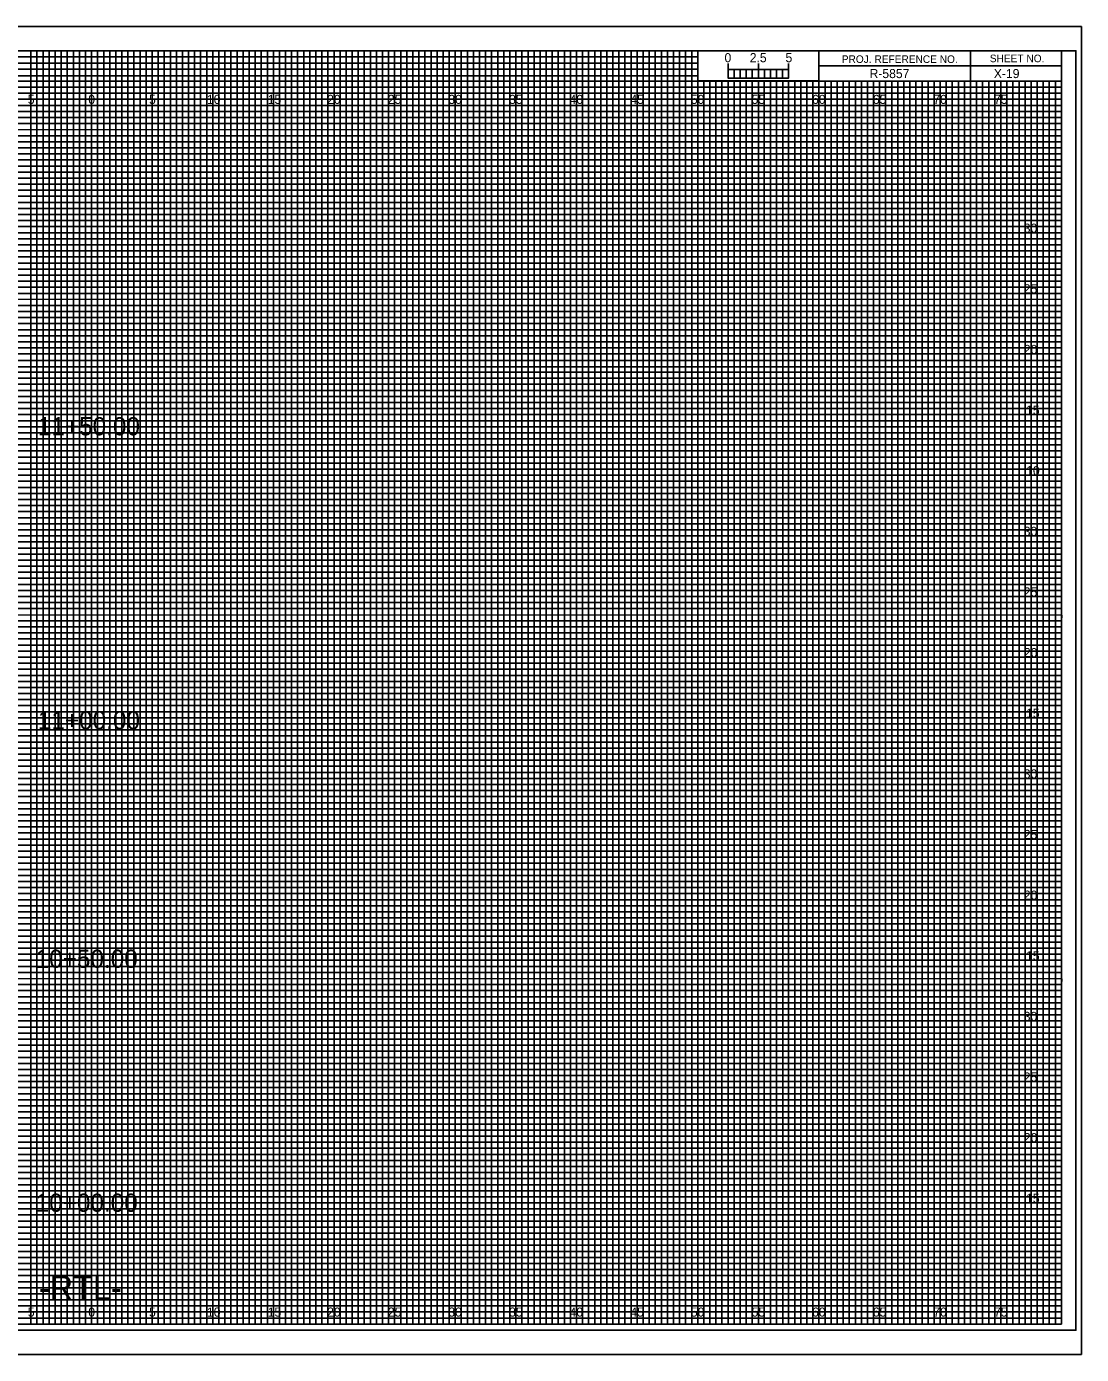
# Model space of a CAD drawing. Extents: x -7 to 162, y -3 to 107.
# Drawn here: x 74.6 to 161.7, y -2.5 to 107 of the extents above; entities that cross this region are included whole.
import ezdxf

# ---------------------------------------------------------------- set-up
doc = ezdxf.new("R2010")
doc.units = 0
for name, color, linetype in [('Exist Cross Section Cell', 7, 'Continuous'), ('Exist XS Center Line Elevation Label', 7, 'Continuous'), ('Exist XS Ground Line', 7, 'Continuous'), ('Prop CMT Pvmt Course 1', 7, 'Continuous'), ('Prop CMT Pvmt Course 1 Wedge', 7, 'Continuous'), ('Prop CMT Pvmt Course 2', 7, 'Continuous'), ('Prop CMT Pvmt Course 2 Wedge', 7, 'Continuous'), ('Prop CMT Pvmt Course 3', 7, 'Continuous'), ('Prop CMT Pvmt Course 3 Wedge', 7, 'Continuous'), ('Prop CMT Pvmt Surface', 7, 'Continuous'), ('Prop CMT Pvmt Surface Shoulder', 7, 'Continuous'), ('Prop CMT Shld Paved Course 1', 7, 'Continuous'), ('Prop CMT Shld Paved Course 2', 7, 'Continuous'), ('Prop CMT Shld Paved Course 3', 7, 'Continuous'), ('Prop CMT Slope Grass', 7, 'Continuous'), ('Prop CMT Subgrade Earthwork', 7, 'Continuous'), ('Scratch_Level_0', 7, 'Continuous')]:
    doc.layers.add(name, color=color, linetype=linetype)

msp = doc.modelspace()

# ---------------------------------------------------------------- linework, layer by layer
at = {"layer": 'Exist XS Center Line Elevation Label'}
for points in [[(72.5, 0), (77.5, 0), (77.5, 105), (82.5, 105), (82.5, 0), (87.5, 0), (87.5, 105), (92.5, 105), (92.5, 0), (97.5, 0), (97.5, 105), (102.5, 105), (102.5, 0), (107.5, 0), (107.5, 105), (112.5, 105), (112.5, 0), (117.5, 0), (117.5, 105), (122.5, 105), (122.5, 0), (127.5, 0), (127.5, 105), (129.97, 105), (130, 105), (130, 102.5), (132.5, 102.5), (132.5, 0), (137.5, 0), (137.5, 102.5), (142.5, 102.5), (142.5, 0), (147.5, 0), (147.5, 102.5), (152.5, 102.5), (152.5, 0), (157.5, 0), (157.5, 102.5)], [(0, 102.5), (137.5, 102.5)], [(0, 92.5), (160, 92.5), (160, 97.5), (0, 97.5)], [(0, 82.5), (160, 82.5), (160, 87.5), (0, 87.5)], [(0, 72.5), (160, 72.5), (160, 77.5), (0, 77.5)], [(0, 62.5), (160, 62.5), (160, 67.5), (0, 67.5)], [(0, 52.5), (160, 52.5), (160, 57.5), (0, 57.5)], [(0, 42.5), (160, 42.5), (160, 47.5), (0, 47.5)], [(0, 32.5), (160, 32.5), (160, 37.5), (0, 37.5)], [(0, 22.5), (160, 22.5), (160, 27.5), (0, 27.5)], [(0, 12.5), (160, 12.5), (160, 17.5), (0, 17.5)], [(0, 2.5), (160, 2.5), (160, 7.5), (0, 7.5)]]:
    msp.add_lwpolyline(points, dxfattribs=at)
at = {"layer": 'Exist XS Ground Line'}
for p, q in [((75, 105), (70, 105)), ((75, 0), (75, 105)), ((85, 105), (80, 105)), ((80, 105), (80, 0)), ((85, 0), (85, 105)), ((95, 105), (90, 105)), ((90, 105), (90, 0)), ((95, 0), (95, 105)), ((105, 105), (100, 105)), ((100, 105), (100, 0)), ((105, 0), (105, 105)), ((115, 105), (110, 105)), ((110, 105), (110, 0)), ((115, 0), (115, 105)), ((125, 105), (120, 105)), ((120, 105), (120, 0)), ((125, 0), (125, 105)), ((130, 105), (130, 0)), ((135, 0), (135, 102.5)), ((145, 102.5), (140, 102.5)), ((140, 102.5), (140, 0)), ((145, 0), (145, 102.5)), ((155, 102.5), (150, 102.5)), ((150, 102.5), (150, 0)), ((155, 0), (155, 102.5)), ((80, 0), (75, 0)), ((90, 0), (85, 0)), ((100, 0), (95, 0)), ((110, 0), (105, 0)), ((120, 0), (115, 0)), ((130, 0), (125, 0)), ((140, 0), (135, 0)), ((150, 0), (145, 0)), ((160, 0), (155, 0)), ((160, 0), (160, 0))]:
    msp.add_line(p, q, dxfattribs=at)
for points in [[(0, 100), (160, 100), (160, 95), (0, 95)], [(0, 90), (160, 90), (160, 85), (0, 85)], [(0, 80), (160, 80), (160, 75), (0, 75)], [(0, 70), (160, 70), (160, 65), (0, 65)], [(0, 60), (160, 60), (160, 55), (0, 55)], [(0, 50), (160, 50), (160, 45), (0, 45)], [(0, 40), (160, 40), (160, 35), (0, 35)], [(0, 30), (160, 30), (160, 25), (0, 25)], [(0, 20), (160, 20), (160, 15), (0, 15)], [(0, 10), (160, 10), (160, 5), (0, 5)]]:
    msp.add_lwpolyline(points, dxfattribs=at)
at = {"layer": 'Prop CMT Pvmt Course 2'}
msp.add_lwpolyline([(-6.7, -2.5), (161.65, -2.5), (161.65, 107), (-6.7, 107)], close=True, dxfattribs=at)
at = {"layer": 'Prop CMT Pvmt Course 3'}
msp.add_lwpolyline([(-5.4, -0.5), (161.2, -0.5), (161.2, 105), (-5.4, 105)], close=True, dxfattribs=at)
at = {"layer": 'Prop CMT Pvmt Surface'}
for p, q in [((161.65, 107), (-6.7, 107)), ((-6.7, -2.5), (161.65, -2.5))]:
    msp.add_line(p, q, dxfattribs=at)
at = {"layer": 'Prop CMT Shld Paved Course 1'}
for p, q in [((152.5, 105), (152.5, 102.5)), ((152.5, 102.5), (152.5, 105)), ((160, 103.75), (140, 103.75)), ((140, 103.75), (140, 102.5)), ((140, 102.5), (160, 102.5))]:
    msp.add_line(p, q, dxfattribs=at)
for points in [[(160, 105), (0, 105), (0, 0), (160, 0)], [(140, 105), (130, 105), (130, 102.52), (140, 102.52)], [(160, 105), (140, 105), (140, 102.5), (160, 102.5)]]:
    msp.add_lwpolyline(points, close=True, dxfattribs=at)
at = {"layer": 'Prop CMT Shld Paved Course 2'}
for p, q in [((133.5, 102.5), (133, 102.5)), ((133, 102.5), (133, 0)), ((133.5, 0), (133.5, 102.5)), ((134.5, 102.5), (134, 102.5)), ((134, 102.5), (134, 0)), ((134.5, 0), (134.5, 102.5)), ((133, 0), (132.5, 0)), ((134, 0), (133.5, 0))]:
    msp.add_line(p, q, dxfattribs=at)
for points in [[(75, 0), (75.5, 0), (75.5, 105), (76, 105), (76, 0)], [(76, 0), (76.5, 0), (76.5, 105), (77, 105), (77, 0)], [(77.5, 0), (78, 0), (78, 105), (78.5, 105), (78.5, 0)], [(78.5, 0), (79, 0), (79, 105), (79.5, 105), (79.5, 0)], [(80, 0), (80.5, 0), (80.5, 105), (81, 105), (81, 0)], [(81, 0), (81.5, 0), (81.5, 105), (82, 105), (82, 0)], [(82.5, 0), (83, 0), (83, 105), (83.5, 105), (83.5, 0)], [(83.5, 0), (84, 0), (84, 105), (84.5, 105), (84.5, 0)], [(85, 0), (85.5, 0), (85.5, 105), (86, 105), (86, 0)], [(86, 0), (86.5, 0), (86.5, 105), (87, 105), (87, 0)], [(87.5, 0), (88, 0), (88, 105), (88.5, 105), (88.5, 0)], [(88.5, 0), (89, 0), (89, 105), (89.5, 105), (89.5, 0)], [(90, 0), (90.5, 0), (90.5, 105), (91, 105), (91, 0)], [(91, 0), (91.5, 0), (91.5, 105), (92, 105), (92, 0)], [(92.5, 0), (93, 0), (93, 105), (93.5, 105), (93.5, 0)], [(93.5, 0), (94, 0), (94, 105), (94.5, 105), (94.5, 0)], [(95, 0), (95.5, 0), (95.5, 105), (96, 105), (96, 0)], [(96, 0), (96.5, 0), (96.5, 105), (97, 105), (97, 0)], [(97.5, 0), (98, 0), (98, 105), (98.5, 105), (98.5, 0)], [(98.5, 0), (99, 0), (99, 105), (99.5, 105), (99.5, 0)], [(100, 0), (100.5, 0), (100.5, 105), (101, 105), (101, 0)], [(101, 0), (101.5, 0), (101.5, 105), (102, 105), (102, 0)], [(102.5, 0), (103, 0), (103, 105), (103.5, 105), (103.5, 0)], [(103.5, 0), (104, 0), (104, 105), (104.5, 105), (104.5, 0)], [(105, 0), (105.5, 0), (105.5, 105), (106, 105), (106, 0)], [(106, 0), (106.5, 0), (106.5, 105), (107, 105), (107, 0)], [(107.5, 0), (108, 0), (108, 105), (108.5, 105), (108.5, 0)], [(108.5, 0), (109, 0), (109, 105), (109.5, 105), (109.5, 0)], [(110, 0), (110.5, 0), (110.5, 105), (111, 105), (111, 0)], [(111, 0), (111.5, 0), (111.5, 105), (112, 105), (112, 0)], [(112.5, 0), (113, 0), (113, 105), (113.5, 105), (113.5, 0)], [(113.5, 0), (114, 0), (114, 105), (114.5, 105), (114.5, 0)], [(115, 0), (115.5, 0), (115.5, 105), (116, 105), (116, 0)], [(116, 0), (116.5, 0), (116.5, 105), (117, 105), (117, 0)], [(117.5, 0), (118, 0), (118, 105), (118.5, 105), (118.5, 0)], [(118.5, 0), (119, 0), (119, 105), (119.5, 105), (119.5, 0)], [(120, 0), (120.5, 0), (120.5, 105), (121, 105), (121, 0)], [(121, 0), (121.5, 0), (121.5, 105), (122, 105), (122, 0)], [(122.5, 0), (123, 0), (123, 105), (123.5, 105), (123.5, 0)], [(123.5, 0), (124, 0), (124, 105), (124.5, 105), (124.5, 0)], [(125, 0), (125.5, 0), (125.5, 105), (126, 105), (126, 0)], [(126, 0), (126.5, 0), (126.5, 105), (127, 105), (127, 0)], [(127.5, 0), (128, 0), (128, 105), (128.5, 105), (128.5, 0)], [(128.5, 0), (129, 0), (129, 105), (129.5, 105), (129.5, 0)], [(130, 0), (130.5, 0), (130.5, 102.5), (131.01, 102.5), (131.01, 0)], [(131, 0), (131.5, 0), (131.5, 102.5), (132, 102.5), (132, 0)], [(135, 0), (135.49, 0), (135.49, 102.5), (136, 102.5), (136, 0)], [(136, 0), (136.5, 0), (136.5, 102.5), (137.03, 102.5), (137.03, 0)], [(137.5, 0), (138, 0), (138, 102.5), (138.5, 102.5), (138.5, 0)], [(138.5, 0), (139, 0), (139, 102.5), (139.5, 102.5), (139.5, 0)], [(140, 0), (140.5, 0), (140.5, 102.5), (141, 102.5), (141, 0)], [(141, 0), (141.5, 0), (141.5, 102.5), (142, 102.5), (142, 0)], [(142.5, 0), (143, 0), (143, 102.5), (143.5, 102.5), (143.5, 0)], [(143.5, 0), (144, 0), (144, 102.5), (144.5, 102.5), (144.5, 0)], [(145, 0), (145.5, 0), (145.5, 102.5), (146, 102.5), (146, 0)], [(146, 0), (146.5, 0), (146.5, 102.5), (147, 102.5), (147, 0)], [(147.5, 0), (148, 0), (148, 102.5), (148.5, 102.5), (148.5, 0)], [(148.5, 0), (149, 0), (149, 102.5), (149.5, 102.5), (149.5, 0)], [(150, 0), (150.5, 0), (150.5, 102.5), (151, 102.5), (151, 0)], [(151, 0), (151.5, 0), (151.5, 102.5), (152, 102.5), (152, 0)], [(152.5, 0), (153, 0), (153, 102.5), (153.5, 102.5), (153.5, 0)], [(153.5, 0), (154, 0), (154, 102.5), (154.5, 102.5), (154.5, 0)], [(155, 0), (155.5, 0), (155.5, 102.5), (156, 102.5), (156, 0)], [(156, 0), (156.5, 0), (156.5, 102.5), (157, 102.5), (157, 0)], [(157.5, 0), (158, 0), (158, 102.5), (158.5, 102.5), (158.5, 0)], [(158.5, 0), (159, 0), (159, 102.5), (159.5, 102.5), (159.5, 0)]]:
    msp.add_lwpolyline(points, dxfattribs=at)
at = {"layer": 'Prop CMT Shld Paved Course 3'}
for p, q in [((132.5, 102.75), (132.5, 103.95)), ((132.5, 103.45), (132.5, 103.95)), ((135, 102.75), (135, 103.95)), ((137.5, 102.75), (137.5, 103.95)), ((137.5, 103.45), (137.5, 103.95))]:
    msp.add_line(p, q, dxfattribs=at)
for points in [[(137.5, 103.45), (132.5, 103.45), (132.5, 102.75), (137.5, 102.75)], [(132.5, 103.45), (133, 103.45), (133, 102.75), (132.5, 102.75)], [(133.5, 103.45), (134, 103.45), (134, 102.75), (133.5, 102.75)], [(134.5, 103.45), (135, 103.45), (135, 102.75), (134.5, 102.75)], [(135.5, 103.45), (136, 103.45), (136, 102.75), (135.5, 102.75)], [(136.5, 103.45), (137, 103.45), (137, 102.75), (136.5, 102.75)]]:
    msp.add_lwpolyline(points, close=True, dxfattribs=at)
at = {"layer": 'Prop CMT Subgrade Earthwork'}
for p, q in [((75, 0), (75, 105)), ((80, 0), (80, 105)), ((85, 0), (85, 105)), ((90, 0), (90, 105)), ((95, 0), (95, 105)), ((100, 0), (100, 105)), ((105, 0), (105, 105)), ((110, 0), (110, 105)), ((115, 0), (115, 105)), ((120, 0), (120, 105)), ((125, 0), (125, 105)), ((130, 0), (130, 102.34)), ((135, 0), (135, 102.34)), ((140, 0), (140, 102.34)), ((145, 0), (145, 102.34)), ((150, 0), (150, 102.34)), ((155, 0), (155, 102.34)), ((0, 100), (160, 100)), ((0, 95), (160, 95)), ((0, 90), (160, 90)), ((0, 85), (160, 85)), ((0, 80), (160, 80)), ((0, 75), (160, 75)), ((0, 70), (160, 70)), ((0, 65), (160, 65)), ((0, 60), (160, 60)), ((0, 55), (160, 55)), ((0, 50), (160, 50)), ((0, 45), (160, 45)), ((0, 40), (160, 40)), ((0, 35), (160, 35)), ((0, 30), (160, 30)), ((0, 25), (160, 25)), ((0, 20), (160, 20)), ((0, 15), (160, 15)), ((0, 10), (160, 10)), ((0, 5), (160, 5))]:
    msp.add_line(p, q, dxfattribs=at)
at = {"layer": 'Scratch_Level_0'}
for p, q in [((0, 104.5), (130, 104.5)), ((130, 104.5), (130, 103.99)), ((130, 103.99), (0, 103.99)), ((0, 103.5), (130, 103.5)), ((130, 102.95), (0, 102.95)), ((130, 103.5), (130, 102.95)), ((0, 102), (160, 102))]:
    msp.add_line(p, q, dxfattribs=at)
for points in [[(0, 101.5), (135, 101.5), (160, 101.5), (160, 101), (0, 101)], [(0, 100.5), (160, 100.5), (160, 99.5), (0, 99.5)], [(0, 99), (160, 99), (160, 98.5), (0, 98.49)], [(0, 98), (160, 98), (160, 97), (0, 97)], [(0, 96.5), (160, 96.5), (160, 96), (0, 96)], [(0, 95.5), (160, 95.5), (160, 94.5), (0, 94.5)], [(0, 94), (160, 94), (160, 93.5), (0, 93.5)], [(0, 93), (160, 93), (160, 92), (0, 92)], [(0, 91.5), (160, 91.5), (160, 91), (0, 91)], [(0, 90.5), (160, 90.5), (160, 89.5), (0, 89.5)], [(0, 89), (160, 89), (160, 88.5), (0, 88.5)], [(0, 88), (160, 88), (160, 86.98), (160, 86.5), (160, 86), (0, 86)], [(0, 87), (160, 87), (160, 86.5), (0, 86.5)], [(0, 85.5), (160, 85.5), (160, 84.5), (0, 84.52)], [(0, 84.52), (160, 84.5), (160, 84), (0, 84)], [(0, 83.5), (160, 83.5), (160, 83), (0, 83)], [(0, 82), (160, 82), (160, 81.5), (0, 81.5)], [(0, 81), (160, 81), (160, 80.5), (0, 80.5)], [(-0.04, 79.45), (160, 79.45), (160, 78.94), (-0.04, 78.94)], [(0, 78.5), (160, 78.5), (160, 78), (0, 78)], [(0, 77), (160, 77), (160, 76.5), (0, 76.5)], [(0, 76), (160, 76), (160, 75.5), (0, 75.5)], [(0, 74.5), (160, 74.5), (160, 74), (0, 74)], [(0, 73.5), (160, 73.5), (160, 73), (0, 73)], [(0, 72), (160, 72), (160, 71.5), (0, 71.5)], [(0, 71), (160, 71), (160, 70.5), (0, 70.5)], [(0, 69.5), (160, 69.5), (160, 68.99), (0, 69)], [(0, 68.5), (160, 68.5), (160, 68), (0, 68)], [(0, 67), (160, 67), (160, 66.5), (0, 66.5)], [(0, 66), (160, 66), (160, 65.5), (0, 65.5)], [(0, 64.5), (160, 64.5), (160, 64), (0, 64)], [(0, 63.5), (160, 63.5), (160, 63), (0, 63)], [(0, 62), (160, 62), (160, 61.5), (0, 61.5)], [(0, 61), (160, 61), (160, 60.5), (0, 60.5)], [(0, 59.5), (160, 59.5), (160, 59), (0, 59)], [(0, 58.5), (160.03, 58.45), (160, 58), (0, 58)], [(0, 57), (160, 57), (160, 56.5), (0, 56.5)], [(0, 56), (160, 56), (160, 55.5), (0, 55.5)], [(0, 54.5), (160, 54.5), (160, 54), (0, 54)], [(0, 53.5), (160, 53.5), (160, 53), (0, 53)], [(0, 52), (160, 52), (160, 51.5), (0, 51.5)], [(0, 51), (160, 51), (160, 50.5), (0, 50.5)], [(0, 49.5), (160, 49.5), (160, 49), (0, 49)], [(0, 48.5), (160, 48.5), (160, 48), (0, 48)], [(0, 47), (160, 47), (160, 46.5), (0, 46.5)], [(0, 46), (160, 46), (160, 45.5), (0, 45.5)], [(0, 44.5), (160, 44.5), (160, 44), (0, 44)], [(0, 43.5), (160, 43.5), (160, 43), (0, 43)], [(0, 42), (160, 42), (160, 41.5), (0, 41.5)], [(0, 41), (160, 41), (160, 40.5), (0, 40.5)], [(0, 39.5), (160, 39.5), (160, 38.99), (0, 39)], [(0, 38.5), (160, 38.5), (160, 38), (0, 38)], [(0, 37), (160, 37), (160, 36.5), (0, 36.5)], [(0, 36), (160, 36), (160, 35.5), (0, 35.5)], [(0, 34.5), (160, 34.5), (160, 34), (0, 34)], [(0, 33.5), (160, 33.5), (160, 33), (0, 33)], [(0, 32), (160, 32), (160, 31.5), (0, 31.5)], [(0, 31), (160, 31), (160, 30.5), (0, 30.5)], [(0, 29.5), (160, 29.5), (160, 29), (0, 29)], [(0, 28.5), (160.03, 28.46), (160, 28), (0, 28)], [(0, 27), (160, 27), (160, 26.5), (0, 26.5)], [(0, 26), (160, 26), (160, 25.5), (0, 25.5)], [(0, 24.5), (160, 24.5), (160, 24), (0, 24)], [(0, 23.5), (160, 23.5), (160, 23), (0, 23)], [(0, 22), (160, 22), (160, 21.5), (0, 21.5)], [(0, 21), (160, 21), (160, 20.5), (0, 20.5)], [(0, 19.5), (160, 19.5), (160, 19), (0, 19)], [(0, 18.5), (160, 18.5), (160, 18), (0, 18)], [(0, 17), (160, 17), (160, 16.5), (0, 16.5)], [(0, 16), (160, 16), (160, 15.5), (0, 15.5)], [(0, 14.5), (160, 14.5), (160, 14), (0, 14)], [(0, 13.5), (160, 13.5), (160, 13), (0, 13)], [(0, 12), (160, 12), (160, 11.5), (0, 11.5)], [(0, 11), (160, 11), (160, 10.5), (0, 10.5)], [(0, 9.5), (160, 9.5), (160, 9), (0, 9)], [(0, 8.5), (160, 8.5), (160, 8), (0, 8)], [(0, 7), (160, 7), (160, 6.5), (0, 6.5)], [(0, 6), (160, 6), (160, 5.5), (0, 5.5)], [(0, 4.5), (160, 4.5), (160, 4), (0, 4)], [(0, 3.5), (160, 3.5), (160, 3), (0, 3)], [(0, 2), (160, 2), (160, 1.5), (0, 1.5)], [(0, 1), (160, 1), (160, 0.5), (0, 0.5)]]:
    msp.add_lwpolyline(points, dxfattribs=at)

# ---------------------------------------------------------------- texts
at = {"layer": 'Exist Cross Section Cell'}
for s, p in [('5', (74.74, 100.62)), ('0', (79.73, 100.62)), ('0', (79.73, 100.62)), ('5', (84.74, 100.62)), ('10', (89.52, 100.62)), ('15', (94.53, 100.62)), ('20', (99.43, 100.62)), ('25', (104.44, 100.62)), ('30', (109.43, 100.62)), ('35', (114.44, 100.62)), ('40', (119.43, 100.62)), ('45', (124.44, 100.62)), ('50', (129.43, 100.62)), ('55', (134.44, 100.62)), ('60', (139.43, 100.62)), ('65', (144.44, 100.62)), ('70', (149.43, 100.62)), ('75', (154.44, 100.62)), ('5', (74.74, 0.62)), ('0', (79.73, 0.62)), ('0', (79.73, 0.62)), ('5', (84.74, 0.62)), ('10', (89.52, 0.62)), ('15', (94.53, 0.62)), ('20', (99.43, 0.62)), ('25', (104.44, 0.62)), ('30', (109.43, 0.62)), ('35', (114.44, 0.62)), ('40', (119.43, 0.62)), ('45', (124.44, 0.62)), ('50', (129.43, 0.62)), ('55', (134.44, 0.62)), ('60', (139.43, 0.62)), ('65', (144.44, 0.62)), ('70', (149.43, 0.62)), ('75', (154.44, 0.62))]:
    msp.add_text(s, height=0.75, dxfattribs=at).set_placement(p)
at = {"layer": 'Prop CMT Pvmt Course 1'}
for s, p in [('11+50.00', (75.57, 73.29)), ('11+00.00', (75.57, 49.05)), ('10+50.00', (75.39, 29.38)), ('10+00.00', (75.39, 9.26))]:
    msp.add_text(s, height=1.5, dxfattribs=at).set_placement(p)
at = {"layer": 'Prop CMT Pvmt Course 1 Wedge'}
msp.add_text('R-5857', height=0.75, dxfattribs=at).set_placement((144.17, 102.75))
at = {"layer": 'Prop CMT Pvmt Course 2 Wedge'}
msp.add_text('-RTL-', height=2, dxfattribs=at).set_placement((75.66, 2))
at = {"layer": 'Prop CMT Pvmt Course 3 Wedge'}
for s, p in [('2.5', (134.29, 104.06)), ('5', (137.24, 104.06))]:
    msp.add_text(s, height=0.75, dxfattribs=at).set_placement(p)
at = {"layer": 'Prop CMT Pvmt Surface Shoulder'}
for s, p in [('30', (156.89, 90)), ('25', (156.89, 85)), ('20', (156.9, 80)), ('15', (157.08, 75)), ('10', (157.09, 70)), ('30', (156.89, 65)), ('25', (156.89, 60)), ('20', (156.9, 55)), ('15', (157.08, 50)), ('30', (156.89, 45)), ('25', (156.89, 40)), ('20', (156.9, 35)), ('15', (157.08, 30)), ('30', (156.89, 25)), ('25', (156.89, 20)), ('20', (156.9, 15)), ('15', (157.08, 10))]:
    msp.add_text(s, height=0.75, dxfattribs=at).set_placement(p)
at = {"layer": 'Prop CMT Shld Paved Course 1'}
for s, p in [('PROJ. REFERENCE NO.', (141.88, 104)), ('SHEET NO.', (154.09, 104.06))]:
    msp.add_text(s, height=0.625, dxfattribs=at).set_placement(p)
at = {"layer": 'Prop CMT Shld Paved Course 3'}
msp.add_text('0', height=0.75, dxfattribs=at).set_placement((132.21, 104.06))
at = {"layer": 'Prop CMT Slope Grass'}
msp.add_text('X-19', height=0.75, dxfattribs=at).set_placement((154.42, 102.75))

doc.saveas('drawing.dxf')
